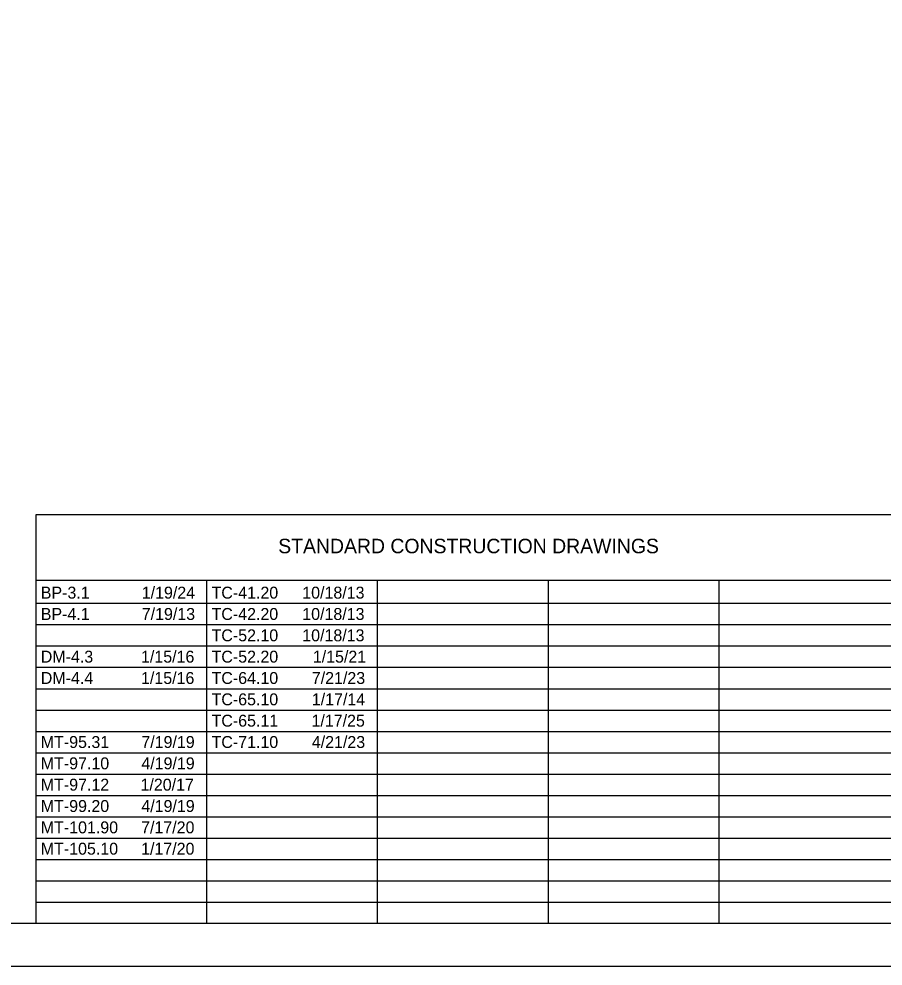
# Model space of a CAD drawing. Extents: x 0 to 170000, y 0 to 110000.
# Drawn here: x 49747 to 100344, y 0 to 55484 of the extents above; entities that cross this region are included whole.
import ezdxf

# ---------------------------------------------------------------- set-up
doc = ezdxf.new("R2010")
doc.units = 0
for name, color, linetype in [('SH_Border', 7, 'Continuous'), ('SH_Cut_Line', 7, 'Continuous'), ('SH_Data', 7, 'Continuous'), ('SH_Text', 7, 'Continuous')]:
    doc.layers.add(name, color=color, linetype=linetype)

msp = doc.modelspace()

# ---------------------------------------------------------------- linework, layer by layer
at = {"layer": 'SH_Border'}
msp.add_lwpolyline([(7500, 107500), (167500, 107500), (167500, 2500), (7500, 2500)], close=True, dxfattribs=at)
at = {"layer": 'SH_Cut_Line'}
msp.add_lwpolyline([(0, 0), (170000, 0), (170000, 110000), (0, 110000)], close=True, dxfattribs=at)
at = {"layer": 'SH_Data'}
for p, q in [((50750, 26459), (118000, 26459)), ((50750, 2500), (50750, 26459)), ((50750, 22605), (118000, 22605)), ((60750, 2500), (60750, 22605)), ((70750, 2500), (70750, 22605)), ((80750, 2500), (80750, 22605)), ((90750, 2500), (90750, 22605)), ((50750, 21250), (118000, 21250)), ((50750, 20000), (118000, 20000)), ((50750, 18750), (118000, 18750)), ((50750, 17500), (118000, 17500)), ((50750, 16250), (118000, 16250)), ((50750, 15000), (118000, 15000)), ((50750, 13750), (118000, 13750)), ((50750, 12500), (118000, 12500)), ((50750, 11250), (118000, 11250)), ((50750, 10000), (118000, 10000)), ((50750, 8750), (118000, 8750)), ((50750, 7500), (118000, 7500)), ((50750, 6250), (118000, 6250)), ((50750, 5000), (118000, 5000)), ((50750, 3750), (118000, 3750))]:
    msp.add_line(p, q, dxfattribs=at)

# ---------------------------------------------------------------- texts
at = {"layer": 'SH_Text'}
for s, height, p in [('STANDARD CONSTRUCTION DRAWINGS', 850, (64928, 24182)), ('BP-3.1', 700, (51025, 21525)), ('1/19/24', 700, (56937, 21525)), ('TC-41.20', 700, (61025, 21525)), ('10/18/13', 700, (66336, 21525)), ('BP-4.1', 700, (51025, 20275)), ('7/19/13', 700, (56937, 20275)), ('TC-42.20', 700, (61025, 20275)), ('10/18/13', 700, (66336, 20275)), ('TC-52.10', 700, (61025, 19025)), ('10/18/13', 700, (66336, 19025)), ('DM-4.3', 700, (51025, 17775)), ('1/15/16', 700, (56894, 17775)), ('TC-52.20', 700, (61025, 17775)), ('1/15/21', 700, (66955, 17775)), ('DM-4.4', 700, (51025, 16525)), ('1/15/16', 700, (56894, 16525)), ('TC-64.10', 700, (61025, 16525)), ('7/21/23', 700, (66895, 16525)), ('TC-65.10', 700, (61025, 15275)), ('1/17/14', 700, (66895, 15275)), ('TC-65.11', 700, (61025, 14025)), ('1/17/25', 700, (66878, 14025)), ('MT-95.31', 700, (51025, 12775)), ('7/19/19', 700, (56914, 12775)), ('TC-71.10', 700, (61025, 12775)), ('4/21/23', 700, (66895, 12775)), ('MT-97.10', 700, (51025, 11525)), ('4/19/19', 700, (56914, 11525)), ('MT-97.12', 700, (51025, 10275)), ('1/20/17', 700, (56865, 10275)), ('MT-99.20', 700, (51025, 9025)), ('4/19/19', 700, (56914, 9025)), ('MT-101.90', 700, (51025, 7775)), ('7/17/20', 700, (56900, 7775)), ('MT-105.10', 700, (51025, 6525)), ('1/17/20', 700, (56900, 6525))]:
    msp.add_text(s, height=height, dxfattribs=at).set_placement(p)

doc.saveas('drawing.dxf')
